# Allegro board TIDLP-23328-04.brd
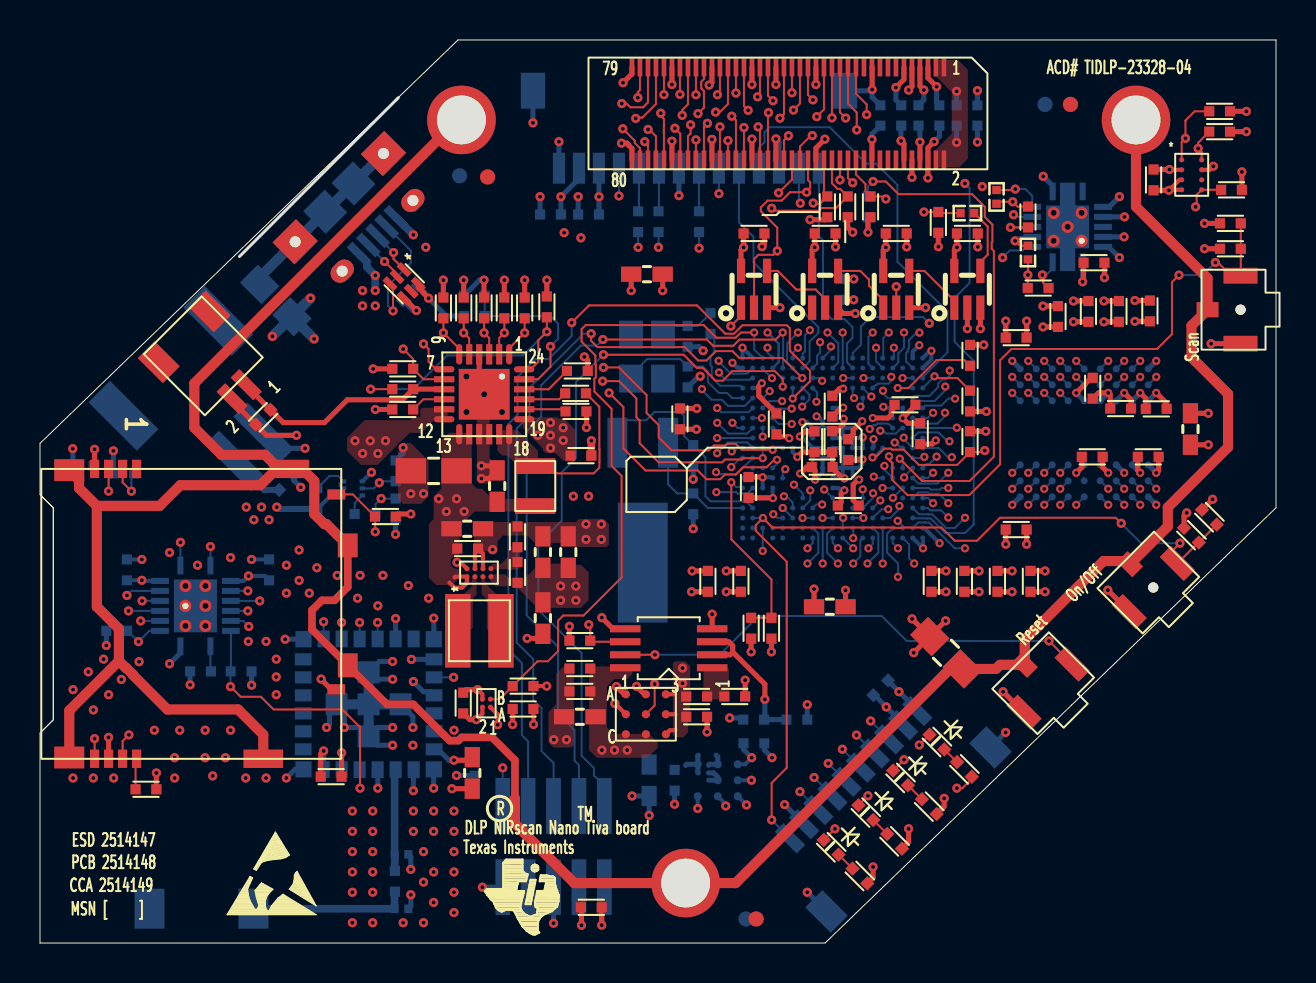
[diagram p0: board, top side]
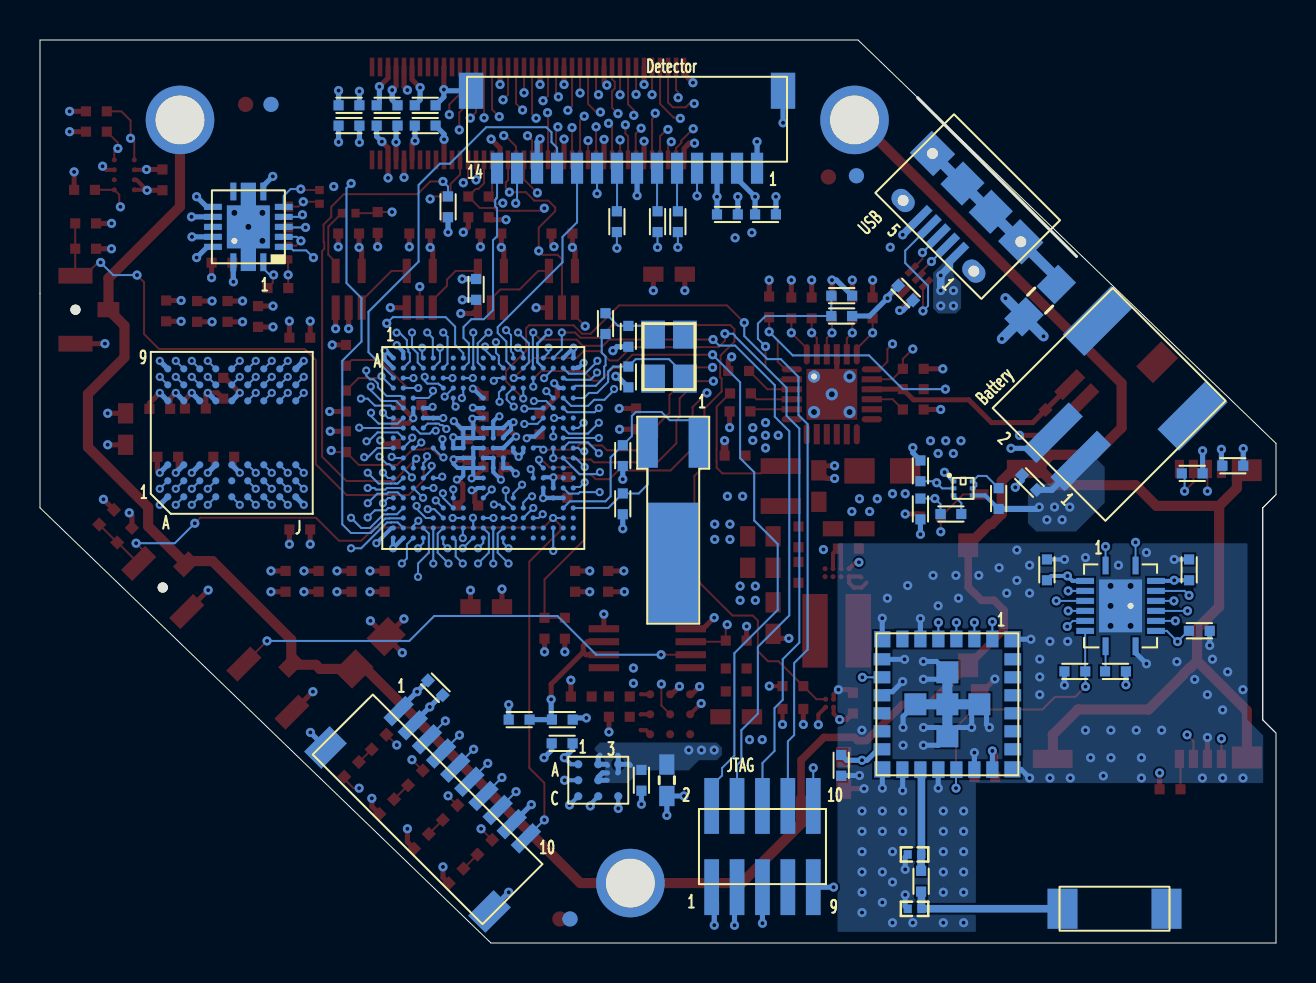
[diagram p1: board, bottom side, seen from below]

Outline 61.81 x 45.18 mm; copper layers: TOP, LY2-GND, LY3-SIG, LY4-SIG, LY5-PWR, LY6-PWR, LY7-SIG, LY8-SIG, LY9-GND, BOTTOM. Coordinates in mm from the lower left corner of the outline.
Outline path: 0,25 20.9,45.18 61.81,45.18 61.81,32.49 61.81,21.78 51.59,11.91 39.25,0 0,0 0,10.5 0.66,11.17 0.66,21.77 0,22.43 0,25

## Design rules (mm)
net group BT-ANT: nets BT_ANT BT_ANTENNA
net group USB_DAT: nets USB_DAT_N USB_DAT_P
net group CLK: nets HSYNC_CS PCLK SDR_CLK VSYNC_WE VSYNC_WE_B
net group PDATA: nets DATAEN_CMD DATAEN_CMD_B PDATA_00 PDATA_01 PDATA_02 PDATA_03 PDATA_04 PDATA_05 PDATA_06 PDATA_07 PDATA_08 PDATA_09 PDATA_10 PDATA_11 PDATA_12 PDATA_13 PDATA_14 PDATA_15 PDATA_16 PDATA_17 PDATA_18 PDATA_19 PDATA_20 PDATA_21 PDATA_22 PDATA_23
net group PWR: nets BATTERY_THERMISTOR
net group SDR: nets SDR_AD00 SDR_AD01 SDR_AD02 SDR_AD03 SDR_AD04 SDR_AD05 SDR_AD06 SDR_AD07 SDR_AD08 SDR_AD09 SDR_AD10 SDR_AD11 SDR_AD12 SDR_AD13 SDR_AD14 SDR_AD15 SDR_CASZ SDR_CKE SDR_CSZ SDR_LDQM SDR_RASZ SDR_UDQM SDR_WEZ

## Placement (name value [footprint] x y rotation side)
C1  -  [0402]  48.81 20.69 0 top
C2  -  [0402]  52.64 27.75 270 top
C3  -  [0402]  52.62 24.32 180 top
C4  -  [0402]  55.42 24.32 0 top
C5  -  [0402]  55.82 26.72 180 top
C6  -  [0402]  48.81 30.29 0 top
C7  -  [0402]  54.04 26.74 180 top
C8  -  [0603]  57.53 25.71 270 top
C10  -  [0402]  2.16 23.88 180 bottom
C11  -  [0402]  21.74 8.89 270 bottom
C12  -  [0603]  21.62 8.51 270 top
C13  -  [0402]  14.56 8.32 0 top
C14  -  [0402]  18.52 32.52 225 bottom
C15  -  [0402]  11.46 18.67 90 bottom
C17  -  [0201]  18.08 4.43 180 bottom
C18  -  [0201]  18.07 1.71 180 bottom
C19  -  [0402]  4.34 18.67 90 bottom
C20  -  [0402]  21.16 12.01 90 top
C21  -  [0402]  25.53 36.45 180 bottom
C22  -  [0402]  27.43 36.45 180 bottom
C23  -  [0402]  55.68 38.18 270 top
C24  -  [0402]  24.16 11.71 0 top
C25  -  [0402]  42.04 12.77 225 bottom
C26  -  [0402]  59.52 36 180 top
C27  -  [0402]  58.48 21.3 135 top
C28  -  [0402]  27.57 1.79 180 top
C29  -  [0402]  32.66 24.38 90 bottom
C30  -  [0402]  32.66 21.97 90 bottom
C32  -  [0402]  35.56 15.75 270 top
C33  -  [0402]  40.41 24.69 270 top
C34  -  [0402]  39.61 25.09 270 top
C35  -  [0402]  39.11 23.81 0 top
C36  -  [0402]  38.73 25.08 270 top
C37  -  [0402]  44.57 18.09 90 top
C38  -  [0402]  46.22 18.09 90 top
C39  -  [0402]  47.87 18.09 90 top
C40  -  [0402]  49.53 18.09 90 top
C41  -  [0402]  40.41 21.89 0 top
C42  -  [0402]  35.43 22.79 270 top
C43  -  [0402]  33.4 18.09 90 top
C44  -  [0402]  35.05 18.09 90 top
C45  -  [0603]  30.35 33.46 0 top
C46  -  [0402]  50.9 31.34 90 top
C47  -  [0402]  52.43 31.6 90 top
C48  -  [0402]  53.95 31.6 90 top
C49  -  [0402]  55.5 31.62 90 top
C50  -  [0603]  39.49 16.82 0 top
C51  -  [0402]  36.83 25.97 90 top
C52  -  [0402]  39.62 26.86 270 top
C53  -  [0402]  40 32.7 270 bottom
C54  -  [0402]  32 26.22 90 top
C55  -  [0402]  52.7 34.04 0 top
C56  -  [0402]  42.55 41.91 180 bottom
C57  -  [0402]  44.45 41.91 0 bottom
C58  -  [0402]  46.35 40.89 0 bottom
C59  -  [0402]  46.35 41.91 0 bottom
C60  -  [0402]  44.45 40.89 0 bottom
C61  -  [0402]  42.55 40.89 180 bottom
C62  -  [0402]  27.05 24.38 0 top
C63  -  [0402]  26.78 27.5 0 top
C64  -  [0805]  19.68 23.62 0 top
C65  -  [0603]  22.86 22.86 90 top
C66  -  [0402]  21.38 19.73 0 top
C67  -  [0603]  21.36 20.72 0 top
C68  -  [0603]  25.15 16.26 270 top
C69  -  [0603]  26.42 19.56 90 top
C70  -  [0603]  25.15 19.56 90 top
C71  -  [0402]  12.33 23.04 225 bottom
C72  -  [0402]  25.34 31.83 270 top
C73  -  [0402]  31.73 8.14 270 bottom
C74  -  [0603]  30.46 8.14 270 bottom
C75  -  [0402]  35.7 9.99 180 bottom
C76  -  [0402]  26.99 13.73 180 top
C77  -  [0402]  26.8 26.6 180 top
C78  -  [0402]  26.99 12.59 180 top
C79  -  [0603]  26.99 11.32 180 top
C80  -  [0402]  32.84 11.32 180 top
C81  -  [0402]  35.7 35.5 0 top
C82  -  [0402]  39.26 35.5 0 top
C83  -  [0402]  42.82 35.5 0 top
C84  -  [0402]  46.37 35.5 0 top
C85  -  [0402]  43.25 26.93 0 top
C86  -  [0402]  44.01 25.49 270 top
C87  -  [0402]  32.38 28.32 90 bottom
C88  -  [0402]  32.38 30.35 90 bottom
D1  -  [0402DIO]  43.03 8.26 135 top
D2  -  [0402DIO]  41.3 6.53 135 top
D3  -  [0402DIO]  39.56 4.79 135 top
D4  -  [0402DIO]  44.85 10.05 135 top
E1  -  [MOD2-BT-WIFI-LTA-5320_MAG]  8.07 1.71 180 bottom
F1  -  [0805]  11.79 32.14 315 bottom
FID  -  [unnamed#2]  22.38 38.32 0 top
FID#2  -  [unnamed#2]  35.81 1.2 0 top
FID#3  -  [unnamed#2]  51.53 41.95 0 top
FID#4  -  [unnamed#2]  50.26 41.95 180 bottom
FID#5  -  [unnamed#2]  35.3 1.2 180 bottom
FID#6  -  [unnamed#2]  20.98 38.38 180 bottom
J1  -  [CONN5-MICRO-USB-10118194_FCI]  14.97 37.29 45 bottom
J2  -  [CONN14-SM14B-SRSS-TB_JST]  32.45 38.76 180 bottom
J3  -  [CONN10-SM10B-SRSS-TB_JST]  40.69 8.42 45 bottom
J4  -  [CONN10-FTSH-105-01-L-DV-K_SAM]  25.68 4.83 180 bottom
J5  -  [CONN80-SS4_SAM]  37.4 41.5 0 top
J6  -  [CONN2-S2B-PH-SM4-TB_JST]  8.52 26.77 225 bottom
J7  -  [CONN2-SM02B-SRSS-TB_JST]  9.96 27.58 225 top
L1  -  [IND-LPS3015_COIL]  21.97 15.62 0 top
L2  -  [IND-2520_TOKO]  24.77 22.86 270 top
L3  -  [0402]  17.75 3.09 270 bottom
MH1  -  [135RD96]  21.08 41.18 0 top
MH2  -  [135RD96]  54.81 41.18 0 top
MH3  -  [135RD96]  32.28 3 0 top
NOREF  -  []  104.7 -1.3 0 top
NOREF#2  -  []  0.66 21.77 0 top
NOREF#3  -  []  0 10.5 0 top
NOREF#4  -  []  78.98 -18.04 180 top
NOREF#5  -  []  20.9 45.18 0 top
NOREF#6  -  []  0 22.43 0 top
NOREF#7  -  []  0.66 11.17 0 top
NOREF#8  -  []  24.15 2.55 0 top
NOREF#9  -  []  61.81 21.78 0 top
NOREF#10  -  []  0.66 21.77 0 top
NOREF#11  -  []  -21.27 74.61 180 top
NOREF#12  -  []  -83.31 -55.55 0 top
NOREF#13  -  []  20.9 45.18 0 top
NOREF#14  -  []  0 0 0 top
NOREF#15  -  []  39.25 0 0 top
NOREF#16  -  []  78.9 74.61 180 top
NOREF#17  -  []  61.81 21.78 0 top
NOREF#18  -  []  0 0 0 top
NOREF#19  -  []  0 25 0 top
NOREF#20  -  []  11.83 3.2 0 top
P1  -  [CONN8-SCHA-MICRO-SD-B0200_ALPS]  7.56 16.47 270 top
R1  -  [0402]  23.22 31.77 90 top
R2  -  [0402]  20.17 31.77 90 top
R3  -  [0402]  21.19 31.77 90 top
R4  -  [0402]  18.14 28.73 180 top
R5  -  [0402]  4.19 23.5 180 bottom
R6  -  [0402]  5.3 7.69 0 top
R7  -  [0402]  17.27 21.34 0 top
R8  -  [0402]  24.24 31.77 270 top
R9  -  [0402]  22.2 31.77 270 top
R11  -  [0402]  8.03 13.59 180 bottom
R12  -  [0402]  3.84 15.62 180 bottom
R13  -  [0402]  10.06 13.59 0 bottom
R14  -  [0402]  29.91 36.09 270 bottom
R15  -  [0402]  30.93 36.09 270 bottom
R16  -  [0402]  32.96 36.09 270 bottom
R17  -  [0402]  41.53 36.83 270 top
R18  -  [0402]  59.58 37.68 0 top
R19  -  [0402]  58.99 40.59 0 top
R20  -  [0402]  58.99 41.61 0 top
R21  -  [0402]  24.16 12.85 180 top
R22  -  [0402]  44.47 6.82 315 top
R23  -  [0402]  42.73 5.09 315 top
R24  -  [0402]  41 3.35 315 top
R25  -  [0402]  46.51 29.4 90 top
R26  -  [0402]  46.51 27.12 270 top
R27  -  [0402]  59.52 34.73 180 top
R28  -  [0402]  57.58 20.41 135 top
R30  -  [0402]  33.53 30.99 90 bottom
R31  -  [0402]  46.51 25.08 270 top
R32  -  [0402]  36.58 15.75 270 top
R33  -  [0201]  47.83 37.33 270 top
R34  -  [0201]  49.4 34.54 270 top
R35  -  [0402]  39.37 36.83 270 top
R36  -  [0402]  40.39 36.83 270 top
R37  -  [0402]  41.4 36.83 270 bottom
R38  -  [0402]  49.91 32.77 180 top
R39  -  [0402]  49.4 36.32 90 top
R40  -  [0402]  23.88 18.54 90 top
R41  -  [0402]  23.88 20.32 90 top
R42  -  [0402]  46.22 8.69 315 top
R43  -  [0402]  35.69 11.18 0 bottom
R44  -  [0402]  18.14 27.71 0 top
R45  -  [0402]  26.99 15.13 0 top
R46  -  [0402]  37.85 11.18 180 bottom
R47  -  [0402]  11.16 26.3 225 top
R48  -  [0402]  26.87 28.62 180 top
R49  -  [0402]  18.14 26.69 0 top
R50  -  [0402]  32.84 12.33 0 top
R51  -  [0402]  34.74 12.33 180 top
R52  -  [0201]  46.37 36.52 0 top
R53  -  [0402]  44.92 36.05 90 top
R54  -  [0402]  17.78 21.72 90 bottom
R55  -  [0402]  17.78 23.62 90 bottom
R56  -  [0402]  13.87 22.24 270 bottom
R57  -  [0402]  16.26 21.46 180 bottom
R58  -  [0805]  45.3 14.52 135 top
R59  -  [0402]  21.72 31.37 0 bottom
R60  -  [0402]  21.72 32.38 180 bottom
SW1  -  [SW3-B3U-3100P-B_OMR]  60.03 31.68 270 top
SW2  -  [SW3-B3U-3100P-B_OMR]  55.67 17.79 225 top
SW3  -  [SW3-B3U-3100P_OMR]  50.41 12.75 225 top
U1  -  [BGA212-ZAD_TI]  39.64 24.77 180 bottom
U2  -  [BGA54_MICRON]  52.22 25.52 90 bottom
U3  -  [SOIC6-DRY_TI]  18.21 32.98 225 top
U4  -  [PQFP16-RGY_TI]  7.77 16.87 270 bottom
U5  -  [MOD24-MOE_TI]  16.43 11.94 0 bottom
U6  -  [BGA8-YPA008_TI]  57.59 38.43 0 top
U7  -  [BGA4-YFP_TI]  22.32 12 180 top
U9  -  [PQFP14-RGY_TI]  51.39 35.83 90 bottom
U10  -  [PQFP24-RGE_TI]  22.21 27.45 270 top
U11  -  [BGA8-YFG_TI]  21.95 18.53 90 top
U12  -  [BGA8-SIP_TI]  33.89 8.14 180 bottom
U13  -  [SOIC8-DGK_TI]  31.44 14.75 90 top
U14  -  [BGA9-SIP_TI]  30.3 11.44 0 top
U15  -  [SOIC5_DCK_TI]  35.7 32.71 0 top
U16  -  [SOIC5_DCK_TI]  39.26 32.71 0 top
U17  -  [SOIC5_DCK_TI]  42.82 32.71 0 top
U18  -  [SOIC5_DCK_TI]  46.37 32.71 0 top
U19  -  [SOIC6-SOT963_DIO]  15.65 22.75 270 bottom
Y1  -  [CRY3-CMR200T_CIT]  30.14 21.15 90 bottom
Y2  -  [CRY-NX3225A_NDK]  30.35 29.34 90 bottom

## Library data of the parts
C1-C7 C10 C11 C13-C15 C19-C30 C32-C44 C46-C49 C51-C63 C66 C71-C73 C75-C78 C80-C88 L3 R1-R9 R11-R28 R30-R32 R35-R51 R53-R57 R59 R60 = 0402: alternate symbols: (0402-1mm)
C8 C12 C45 C50 C65 C67-C70 C74 C79 = 0603
C17 C18 R33 R34 R52 = 0201: alternate symbols: (0402-1mm)
C64 F1 R58 = 0805
D1-D4 = 0402DIO
E1 = MOD2-BT-WIFI-LTA-5320_MAG
J1 = CONN5-MICRO-USB-10118194_FCI
J2 = CONN14-SM14B-SRSS-TB_JST
J3 = CONN10-SM10B-SRSS-TB_JST
J4 = CONN10-FTSH-105-01-L-DV-K_SAM
J5 = CONN80-SS4_SAM
J6 = CONN2-S2B-PH-SM4-TB_JST
J7 = CONN2-SM02B-SRSS-TB_JST
L1 = IND-LPS3015_COIL
L2 = IND-2520_TOKO
MH1-MH3 = 135RD96
P1 = CONN8-SCHA-MICRO-SD-B0200_ALPS
SW1 SW2 = SW3-B3U-3100P-B_OMR
SW3 = SW3-B3U-3100P_OMR
U1 = BGA212-ZAD_TI
U2 = BGA54_MICRON
U3 = SOIC6-DRY_TI
U4 = PQFP16-RGY_TI
U5 = MOD24-MOE_TI
U6 = BGA8-YPA008_TI
U7 = BGA4-YFP_TI
U9 = PQFP14-RGY_TI
U10 = PQFP24-RGE_TI
U11 = BGA8-YFG_TI
U12 = BGA8-SIP_TI
U13 = SOIC8-DGK_TI
U14 = BGA9-SIP_TI
U15-U18 = SOIC5_DCK_TI
U19 = SOIC6-SOT963_DIO
Y1 = CRY3-CMR200T_CIT
Y2 = CRY-NX3225A_NDK

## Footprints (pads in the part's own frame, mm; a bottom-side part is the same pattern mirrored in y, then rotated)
135RD96
  round 3.429 hole 2.438: 1(0,0)
0201
  rect 0.406x0.432 smd: 1(-0.343,0) 2(0.343,0)
0402
  rect 0.508x0.508 smd: 1(-0.521,0) 2(0.521,0)
0402DIO
  rect 0.508x0.508 smd: 1(-0.521,0) 2(0.521,0)
0603
  rect 1.016x0.762 smd: 1(-0.787,0) 2(0.787,0)
0805
  rect 1.524x1.27 smd: 1(-1.143,0) 2(1.143,0)
BGA4-YFP_TI
  round 0.254 smd: A1(-0.2,0.2) A2(0.2,0.2) B1(-0.2,-0.2) B2(0.2,-0.2)
BGA8-SIP_TI
  round 0.406 smd: A1(-1,0.8) A2(0,0.8) A3(1,0.8) B1(-1,0) B2(0,0) C1(-1,-0.8) C2(0,-0.8) C3(1,-0.8)
BGA8-YFG_TI
  round 0.254 smd: A1(-0.2,0.6) A2(0.2,0.6) B1(-0.2,0.2) B2(0.2,0.2) C1(-0.2,-0.2) C2(0.2,-0.2) D1(-0.2,-0.6) D2(0.2,-0.6)
BGA8-YPA008_TI
  round 0.254 smd: A1(-0.5,0.75) A2(0.5,0.75) B1(-0.5,0.25) B2(0.5,0.25) C1(-0.5,-0.25) C2(0.5,-0.25) D1(-0.5,-0.75) D2(0.5,-0.75)
BGA9-SIP_TI
  round 0.406 smd: A1(-1,1) A2(0,1) A3(1,1) B1(-1,0) B2(0,0) B3(1,0) C1(-1,-1) C2(0,-1) C3(1,-1)
BGA54_MICRON
  round 0.356 smd: A1(-3.2,3.2) A2(-2.4,3.2) A3(-1.6,3.2) A7(1.6,3.2) A8(2.4,3.2) A9(3.2,3.2) B1(-3.2,2.4) B2(-2.4,2.4) B3(-1.6,2.4) B7(1.6,2.4) B8(2.4,2.4) B9(3.2,2.4) C1(-3.2,1.6) C2(-2.4,1.6) C3(-1.6,1.6) C7(1.6,1.6) C8(2.4,1.6) C9(3.2,1.6) D1(-3.2,0.8) D2(-2.4,0.8) D3(-1.6,0.8) D7(1.6,0.8) D8(2.4,0.8) D9(3.2,0.8) E1(-3.2,0) E2(-2.4,0) E3(-1.6,0) E7(1.6,0) E8(2.4,0) E9(3.2,0) F1(-3.2,-0.8) F2(-2.4,-0.8) F3(-1.6,-0.8) F7(1.6,-0.8) F8(2.4,-0.8) F9(3.2,-0.8) G1(-3.2,-1.6) G2(-2.4,-1.6) G3(-1.6,-1.6) G7(1.6,-1.6) G8(2.4,-1.6) G9(3.2,-1.6) H1(-3.2,-2.4) H2(-2.4,-2.4) H3(-1.6,-2.4) H7(1.6,-2.4) H8(2.4,-2.4) H9(3.2,-2.4) J1(-3.2,-3.2) J2(-2.4,-3.2) J3(-1.6,-3.2) J7(1.6,-3.2) J8(2.4,-3.2) J9(3.2,-3.2)
BGA212-ZAD_TI
  round 0.254 smd: A1(-4.5,4.5) A2(-4,4.5) A4(-3,4.5) A5(-2.5,4.5) A7(-1.5,4.5) A8(-1,4.5) A10(0,4.5) A11(0.5,4.5) A13(1.5,4.5) A14(2,4.5) A16(3,4.5) A17(3.5,4.5) A18(4,4.5) A19(4.5,4.5) B1(-4.5,4) B2(-4,4) B3(-3.5,4) B4(-3,4) B5(-2.5,4) B6(-2,4) B7(-1.5,4) B8(-1,4) B9(-0.5,4) B10(0,4) B11(0.5,4) B12(1,4) B13(1.5,4) B14(2,4) B15(2.5,4) B16(3,4) B17(3.5,4) B18(4,4) B19(4.5,4) C1(-4.5,3.5) C2(-4,3.5) C5(-2.5,3.5) C6(-2,3.5) C8(-1,3.5) C10(0,3.5) C12(1,3.5) C14(2,3.5) C15(2.5,3.5) C18(4,3.5) D1(-4.5,3) D2(-4,3) D6(-2,3) D7(-1.5,3) D8(-1,3) D12(1,3) D13(1.5,3) D14(2,3) D18(4,3) D19(4.5,3) E2(-4,2.5) E3(-3.5,2.5) E7(-1.5,2.5) E10(0,2.5) E13(1.5,2.5) E17(3.5,2.5) E18(4,2.5) E19(4.5,2.5) F1(-4.5,2) F2(-4,2) F3(-3.5,2) F4(-3,2) F10(0,2) F16(3,2) F17(3.5,2) F18(4,2) G1(-4.5,1.5) G2(-4,1.5) G4(-3,1.5) G5(-2.5,1.5) G10(0,1.5) G15(2.5,1.5) G16(3,1.5) G18(4,1.5) G19(4.5,1.5) H2(-4,1) H3(-3.5,1) H4(-3,1) H9(-0.5,1) H10(0,1) H11(0.5,1) H12(1,1) H16(3,1) H17(3.5,1) H18(4,1) H19(4.5,1) J1(-4.5,0.5) J2(-4,0.5) J8(-1,0.5) J9(-0.5,0.5) J10(0,0.5) J11(0.5,0.5) J12(1,0.5) J18(4,0.5) K1(-4.5,0) K2(-4,0) K3(-3.5,0) K5(-2.5,0) K6(-2,0) K7(-1.5,0) K8(-1,0) K9(-0.5,0) K10(0,0) K11(0.5,0) K12(1,0) K13(1.5,0) K14(2,0) K15(2.5,0) K17(3.5,0) K18(4,0) K19(4.5,0) L2(-4,-0.5) L8(-1,-0.5) L9(-0.5,-0.5) L10(0,-0.5) L11(0.5,-0.5) L12(1,-0.5) L18(4,-0.5) L19(4.5,-0.5) M1(-4.5,-1) M2(-4,-1) M3(-3.5,-1) M4(-3,-1) M8(-1,-1) M9(-0.5,-1) M10(0,-1) M11(0.5,-1) M12(1,-1) M16(3,-1) M17(3.5,-1) M18(4,-1) N1(-4.5,-1.5) N2(-4,-1.5) N4(-3,-1.5) N5(-2.5,-1.5) N10(0,-1.5) N15(2.5,-1.5) N16(3,-1.5) N18(4,-1.5) N19(4.5,-1.5) P2(-4,-2) P3(-3.5,-2) P4(-3,-2) P10(0,-2) P16(3,-2) P17(3.5,-2) P18(4,-2) P19(4.5,-2) R1(-4.5,-2.5) R2(-4,-2.5) R3(-3.5,-2.5) R7(-1.5,-2.5) R10(0,-2.5) R13(1.5,-2.5) R17(3.5,-2.5) R18(4,-2.5) T1(-4.5,-3) T2(-4,-3) T6(-2,-3) T7(-1.5,-3) T8(-1,-3) T12(1,-3) T13(1.5,-3) T14(2,-3) T18(4,-3) T19(4.5,-3) U2(-4,-3.5) U5(-2.5,-3.5) U6(-2,-3.5) U8(-1,-3.5) U10(0,-3.5) U12(1,-3.5) U14(2,-3.5) U15(2.5,-3.5) U18(4,-3.5) U19(4.5,-3.5) V1(-4.5,-4) V2(-4,-4) V3(-3.5,-4) V4(-3,-4) V5(-2.5,-4) V6(-2,-4) V7(-1.5,-4) V8(-1,-4) V9(-0.5,-4) V10(0,-4) V11(0.5,-4) V12(1,-4) V13(1.5,-4) V14(2,-4) V15(2.5,-4) V16(3,-4) V17(3.5,-4) V18(4,-4) V19(4.5,-4) W1(-4.5,-4.5) W2(-4,-4.5) W3(-3.5,-4.5) W4(-3,-4.5) W6(-2,-4.5) W7(-1.5,-4.5) W9(-0.5,-4.5) W10(0,-4.5) W12(1,-4.5) W13(1.5,-4.5) W15(2.5,-4.5) W16(3,-4.5) W18(4,-4.5) W19(4.5,-4.5)
CONN2-S2B-PH-SM4-TB_JST
  rect 1.524x3.429 smd: (-3.35,2.8) (3.35,2.8)
  rect 1x3.29 smd: 1(1,-2.75) 2(-1,-2.75)
CONN2-SM02B-SRSS-TB_JST
  rect 1.194x1.778 smd: (-1.8,-3.886) (1.8,-3.886)
  rect 0.61x1.6 smd: 1(-0.5,0) 2(0.5,0)
CONN5-MICRO-USB-10118194_FCI
  rect 0.406x1.372 smd: 1(-1.3,2.7) 2(-0.65,2.7) 3(0,2.7) 4(0.65,2.7) 5(1.3,2.7)
  rect 1.65x1.55 hole 0.55: 6(3.122,0) 9(-3.122,0)
  rect 1.524x1.6 smd: 7(1,0) 8(-1,0)
  oval 1.25x0.95 hole 0.55: 10(2.5,2.7) 11(-2.5,2.7)
CONN8-SCHA-MICRO-SD-B0200_ALPS
  rect 0.914x0.457 smd: 1(-7.25,-2.735) 2(-7.25,-3.435) 3(-7.25,-4.135) 4(-7.25,-4.835) 5(7.25,-4.835) 6(7.25,-4.135) 7(7.25,-3.435) 8(7.25,-2.735)
  rect 0.914x1.981 smd: 9(7.25,3.6) 14(-7.25,4.9)
  rect 0.508x0.889 smd: 10(3.775,7.25) 13(-5.975,7.25)
  rect 1.194x0.991 smd: 11(2.575,7.825) 12(-3.425,7.825)
  rect 1.092x1.499 smd: 15(-7.187,-6.1) 16(7.187,-6.1)
CONN10-FTSH-105-01-L-DV-K_SAM
  rect 0.737x2.794 smd: 1(-2.54,-2.032) 2(-2.54,2.032) 3(-1.27,-2.032) 4(-1.27,2.032) 5(0,-2.032) 6(0,2.032) 7(1.27,-2.032) 8(1.27,2.032) 9(2.54,-2.032) 10(2.54,2.032)
CONN10-SM10B-SRSS-TB_JST
  rect 0.61x1.549 smd: 1(4.5,0) 2(3.5,0) 3(2.5,0) 4(1.5,0) 5(0.5,0) 6(-0.5,0) 7(-1.5,0) 8(-2.5,0) 9(-3.5,0) 10(-4.5,0)
  rect 1.219x1.803 smd: 11(-5.8,3.875) 12(5.8,3.875)
CONN14-SM14B-SRSS-TB_JST
  rect 0.61x1.549 smd: 1(6.5,0) 2(5.5,0) 3(4.5,0) 4(3.5,0) 5(2.5,0) 6(1.5,0) 7(0.5,0) 8(-0.5,0) 9(-1.5,0) 10(-2.5,0) 11(-3.5,0) 12(-4.5,0) 13(-5.5,0) 14(-6.5,0)
  rect 1.219x1.803 smd: 15(-7.8,3.875) 16(7.8,3.875)
CONN80-SS4_SAM
  rect 0.229x0.94 smd: 1(7.801,2.324) 2(7.801,-2.324) 3(7.401,2.324) 4(7.401,-2.324) 5(7.001,2.324) 6(7.001,-2.324) 7(6.601,2.324) 8(6.601,-2.324) 9(6.201,2.324) 10(6.201,-2.324) 11(5.801,2.324) 12(5.801,-2.324) 13(5.401,2.324) 14(5.401,-2.324) 15(5.001,2.324) 16(5.001,-2.324) 17(4.601,2.324) 18(4.601,-2.324) 19(4.201,2.324) 20(4.201,-2.324) 21(3.801,2.324) 22(3.801,-2.324) 23(3.401,2.324) 24(3.401,-2.324) 25(3.001,2.324) 26(3.001,-2.324) 27(2.6,2.324) 28(2.6,-2.324) 29(2.2,2.324) 30(2.2,-2.324) 31(1.8,2.324) 32(1.8,-2.324) 33(1.4,2.324) 34(1.4,-2.324) 35(1,2.324) 36(1,-2.324) 37(0.6,2.324) 38(0.6,-2.324) 39(0.2,2.324) 40(0.2,-2.324) 41(-0.2,2.324) 42(-0.2,-2.324) 43(-0.6,2.324) 44(-0.6,-2.324) 45(-1,2.324) 46(-1,-2.324) 47(-1.4,2.324) 48(-1.4,-2.324) 49(-1.8,2.324) 50(-1.8,-2.324) 51(-2.2,2.324) 52(-2.2,-2.324) 53(-2.6,2.324) 54(-2.6,-2.324) 55(-3,2.324) 56(-3,-2.324) 57(-3.4,2.324) 58(-3.4,-2.324) 59(-3.8,2.324) 60(-3.8,-2.324) 61(-4.2,2.324) 62(-4.2,-2.324) 63(-4.6,2.324) 64(-4.6,-2.324) 65(-5,2.324) 66(-5,-2.324) 67(-5.401,2.324) 68(-5.401,-2.324) 69(-5.801,2.324) 70(-5.801,-2.324) 71(-6.201,2.324) 72(-6.201,-2.324) 73(-6.601,2.324) 74(-6.601,-2.324) 75(-7.001,2.324) 76(-7.001,-2.324) 77(-7.401,2.324) 78(-7.401,-2.324) 79(-7.801,2.324) 80(-7.801,-2.324)
CRY3-CMR200T_CIT
  rect 6x2.5 smd: (-2.125,0)
  rect 2.5x1 smd: 1(3.875,-1.27) 2(3.875,1.27)
CRY-NX3225A_NDK
  rect 1.397x1.194 smd: 1(-1.1,-0.8) 2(1.1,-0.8) 3(1.1,0.8) 4(-1.1,0.8)
IND-2520_TOKO
  rect 0.787x2.007 smd: 1(-1,0) 2(1,0)
IND-LPS3015_COIL
  rect 1.27x3.683 smd: 1(-1.079,0) 2(1.079,0)
MOD2-BT-WIFI-LTA-5320_MAG
  rect 1.499x2.007 smd: 1(-2.6,0) 2(2.6,0)
MOD24-MOE_TI
  rect 0.61x0.838 smd: 1(-2.25,-3.269) 2(-1.35,-3.269) 3(-0.45,-3.269) 4(0.45,-3.269) 5(1.35,-3.269) 6(2.25,-3.269) 13(2.25,3.269) 14(1.35,3.269) 15(0.45,3.269) 16(-0.45,3.269) 17(-1.35,3.269) 18(-2.25,3.269)
  rect 0.838x0.61 smd: 7(3.269,-2.25) 8(3.269,-1.35) 9(3.269,-0.45) 10(3.269,0.45) 11(3.269,1.35) 12(3.269,2.25) 19(-3.269,2.25) 20(-3.269,1.35) 21(-3.269,0.45) 22(-3.269,-0.45) 23(-3.269,-1.35) 24(-3.269,-2.25)
  rect 1.1x1.1 smd: 25(0,-1.6) 26(-1.6,0) 27(0,0) 28(1.6,0) 29(0,1.6)
  rect 0.813x0.813 smd: 30(-3.256,-3.256) 31(3.256,-3.256) 32(3.256,3.256) 33(-3.256,3.256)
PQFP14-RGY_TI
  rect 0.889x0.305 smd: 1(-1.77,-0.75) 7(1.77,-0.75) 8(1.77,0.75) 14(-1.77,0.75)
  rect 0.305x0.889 smd: 2(-1,-1.77) 3(-0.5,-1.77) 4(0,-1.77) 5(0.5,-1.77) 6(1,-1.77) 9(1,1.77) 10(0.5,1.77) 11(0,1.77) 12(-0.5,1.77) 13(-1,1.77)
  round 0.61 hole 0.305: 15(-0.7,0.7)
PQFP16-RGY_TI
  rect 0.889x0.305 smd: 1(-2.02,-0.75) 8(2.02,-0.75) 9(2.02,0.75) 16(-2.02,0.75)
  rect 0.305x0.889 smd: 2(-1.25,-1.77) 3(-0.75,-1.77) 4(-0.25,-1.77) 5(0.25,-1.77) 6(0.75,-1.77) 7(1.25,-1.77) 10(1.25,1.77) 11(0.75,1.77) 12(0.25,1.77) 13(-0.25,1.77) 14(-0.75,1.77) 15(-1.25,1.77)
  round 0.61 hole 0.305: 17(0,0.5)
PQFP24-RGE_TI
  oval 1.016x0.305 smd: 1(-2,1.25) 6(-2,-1.25) 13(2,-1.25) 18(2,1.25)
  rect 1.016x0.305 smd: 2(-2,0.75) 3(-2,0.25) 4(-2,-0.25) 5(-2,-0.75) 14(2,-0.75) 15(2,-0.25) 16(2,0.25) 17(2,0.75)
  oval 0.305x1.016 smd: 7(-1.25,-2) 12(1.25,-2) 19(1.25,2) 24(-1.25,2)
  rect 0.305x1.016 smd: 8(-0.75,-2) 9(-0.25,-2) 10(0.25,-2) 11(0.75,-2) 20(0.75,2) 21(0.25,2) 22(-0.25,2) 23(-0.75,2)
  round 0.61 hole 0.305: 25(-0.889,0.889)
SOIC5_DCK_TI
  rect 0.406x1.219 smd: 1(-0.65,-0.92) 2(0,-0.92) 3(0.65,-0.92) 4(0.65,0.92) 5(-0.65,0.92)
SOIC6-DRY_TI
  rect 0.305x0.762 smd: 1(-0.5,-0.506) 2(0,-0.506) 3(0.5,-0.506) 4(0.513,0.506) 5(0.013,0.506) 6(-0.487,0.506)
SOIC6-SOT963_DIO
  rect 0.203x0.279 smd: 1(-0.35,-0.475) 2(0,-0.475) 3(0.35,-0.475) 4(0.35,0.475) 5(0,0.475) 6(-0.35,0.475)
SOIC8-DGK_TI
  rect 0.356x1.524 smd: 1(-0.975,-2.173) 2(-0.325,-2.173) 3(0.325,-2.173) 4(0.975,-2.173) 5(0.975,2.173) 6(0.325,2.173) 7(-0.325,2.173) 8(-0.975,2.173)
SW3-B3U-3100P-B_OMR
  round 0.508 hole 0.889 unplated: (0,0)
  rect 0.787x1.702 smd: 1(-1.7,0) 2(1.7,0)
  rect 0.762x1.092 smd: 3(0,-1.65)
SW3-B3U-3100P_OMR
  rect 0.787x1.702 smd: 1(-1.7,0) 2(1.7,0)
  rect 0.762x1.092 smd: 3(0,-1.65)
unnamed#2
  round 0.762 smd: 1(0,0)

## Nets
GND: C1.2 C2.2 C3.2 C4.2 C5.2 C6.2 C7.2 C8.2 C10.2 C11.2 C12.2 C13.2 C14.2 C15.2 C17.1 C18.1 C19.2 C20.2 C21.2 C22.2 C23.2 C24.2 C25.2 C26.2 C27.2 C28.2 C29.1 C30.1 C32.2 C33.2 C34.2 C35.2 C36.2 C37.2 C38.2 C39.2 C40.2 C41.2 C42.2 C43.2 C44.2 C45.2 C46.2 C47.2 C48.2 C49.2 C50.2 C51.2 C52.2 C53.2 C54.1 C55.2 C56.2 C57.2 C58.2 C59.2 C60.2 C61.2 C62.2 C64.1 C65.2 C66.2 C67.2 C68.2 C69.2 C70.2 C71.1 C72.1 C73.2 C74.2 C75.1 C76.2 C77.1 C78.2 C79.2 C80.1 C81.2 C82.2 C83.2 C84.2 C85.1 C86.2 C87.1 C88.1 F1.2 J1.5 J2.1 J2.7 J2.12 J2.15 J2.16 J3.2 J3.9 J3.11 J3.12 J4.3 J4.5 J4.9 J5.5 J5.6 J5.9 J5.10 J5.19 J5.20 J5.33 J5.34 J5.43 J5.44 J5.49 J5.50 J5.59 J5.60 J5.69 J5.70 J5.79 J5.80 J6.2 J7.2 P1.6 P1.10 R8.1 R9.1 R12.2 R13.2 R21.1 R31.1 R41.2 R46.1 R47.2 R48.1 R49.1 R51.1 R54.1 R55.2 R58.2 R60.2 SW1.2 SW2.2 SW3.2 U1.A1 U1.A2 U1.A18 U1.A19 U1.B1 U1.B19 U1.D18 U1.F10 U1.G4 U1.G5 U1.H10 U1.H11 U1.H12 U1.J11 U1.J12 U1.K6 U1.K9 U1.K10 U1.K13 U1.K14 U1.L8 U1.L9 U1.M8 U1.M9 U1.M10 U1.N10 U1.P16 U1.R17 U1.R18 U1.V1 U1.W1 U1.W2 U2.A1 U2.A3 U2.B7 U2.C3 U2.D7 U2.E3 U2.J1 U3.4 U4.9 U4.17 U5.5 U5.7 U5.9 U5.13 U5.15 U5.17 U5.25 U5.26 U5.27 U5.28 U5.29 U5.30 U5.31 U5.32 U5.33 U6.B2 U6.C1 U6.D1 U7.B2 U9.7 U9.9 U9.10 U9.12 U9.13 U9.15 U10.4 U10.15 U10.16 U10.25 U11.B2 U11.C2 U12.B1 U12.C1 U12.C2 U12.C3 U13.5 U14.A1 U14.A2 U14.B1 U15.3 U16.3 U17.3 U18.3 U19.1
GND_EARTH: MH1.1 MH2.1 MH3.1 P1.9 P1.11 P1.12 P1.14 P1.15 P1.16 R58.1 SW1.3 SW2.3 SW3.3
ANT_PAD: E1.2
BAT_V_SW: R54.2 R57.1 U1.A4
BAT_VSENSE_EN: R55.1 U1.B4 U19.2
BATTERY_THERMISTOR: J7.1 R44.2 R47.1 U10.9
BC_CSZ: R8.2 U1.H4 U10.1
BC_EN1: R1.1 U1.E2 U10.2
BC_EN2: R9.2 U1.E3 U10.3
BC_INT: R4.1 U1.W12 U10.8
BC_SCL: R2.1 U1.V3 U10.6
BC_SDA: R3.1 U1.W3 U10.5
BT1P8_CTS: U4.6 U5.4
BT1P8_NSHUTD: R13.1 U4.7 U5.16
BT1P8_RTS: U4.3 U5.1
BT1P8_RX: U4.5 U5.2
BT1P8_SLOW_CK: U4.1 U5.8
BT1P8_TX: U4.4 U5.3
BT_ANT: C18.2 E1.1 L3.2
BT_ANTENNA: C17.2 L3.1 U5.14
BT_CTS: U1.B12 U4.11
BT_NSHUTD: R12.1 U1.T2 U4.10
BT_RTS: U1.D8 U4.14
BT_RX: U1.C8 U4.12
BT_SLOW_CK: U1.C12 U4.16
BT_TX: U1.E7 U4.13
CSZ: J2.5 R14.1
CSZP: R14.2 U1.C6
DATAEN_CMD: R38.1 U1.N1 U9.1
DATAEN_CMD_B: J5.47 R34.2 R38.2
DIN: J2.8 R16.1
DINP: R16.2 U1.A5
DLPC_HOST_IRQ: J5.23 R37.1 U1.M3
DLPC_XLAT0_TIVA: J5.39 U1.D6
DLPC_XLAT1_TIVA: J5.41 U1.D7
DOUT_S: J2.9 U1.B5
DRDYZ: J2.10 U1.B13
EN: R52.1 R53.2 U11.A2 U14.B2
FLASH_DI_TIVA: J5.25 U1.K17
HSYNC_CS: J5.48 U1.N2
HUM_DRDYZ: R18.1 U1.A8 U6.D2
HUM_SCL: R20.1 U1.F2 U6.A1
HUM_SDA: R19.1 U1.F1 U6.A2
LI-ION_BATTERY: C71.2 J6.1 R56.2 U10.11 U10.12 U19.4
MSD_CARD_DET: P1.13 R7.1 U1.A13
MSD_CLK: P1.5 U1.T7
MSD_CSZ: P1.2 R5.1 U1.W6
MSD_DI: P1.3 U1.V6
MSD_DO: P1.7 U1.U6
OSC0: C87.2 U1.E19 Y2.1
P1P8V: C24.1 C56.1 C61.1 C75.2 J5.11 J5.12 R43.1 U7.A1 U12.A1
P1P8V_BT: C13.1 C15.1 C20.1 R11.2 U4.2 U5.18 U7.A2
P3P3V: C1.1 C2.1 C3.1 C4.1 C5.1 C6.1 C7.1 C8.1 C10.1 C11.1 C12.1 C19.1 C22.1 C23.1 C25.1 C28.1 C33.1 C34.1 C35.1 C36.1 C37.1 C38.1 C39.1 C40.1 C41.1 C42.1 C43.1 C44.1 C45.1 C46.1 C47.1 C48.1 C49.1 C50.1 C55.1 C57.1 C60.1 C68.1 C69.1 C70.1 C85.2 C86.1 J2.3 J3.1 J4.1 J5.7 J5.8 P1.4 R1.2 R2.2 R3.2 R4.2 R5.2 R6.2 R7.2 R17.2 R18.2 R19.2 R20.2 R22.2 R23.2 R24.2 R25.2 R26.2 R27.2 R28.2 R32.2 R35.2 R36.2 R37.2 R40.1 R45.1 U1.F3 U1.F4 U1.G10 U1.H9 U1.J8 U1.J9 U1.J10 U1.K7 U1.K8 U1.K11 U1.K12 U1.L10 U1.L11 U1.L12 U1.M11 U1.M12 U1.N16 U1.P10 U1.P17 U2.A7 U2.A9 U2.B3 U2.C7 U2.D3 U2.E7 U2.J9 U4.15 U5.12 U6.B1 U9.14 U11.D1 U13.4
P5P0V: C21.1 C80.2 J2.2 R50.1 U14.A3 U14.B3 U14.C3
P_LDO_V: C72.2 R42.2 R44.1 U10.24
PAD_INTZ: J5.29 U17.2
PAD_RSTZ: J5.31 U15.1
PAD_RSTZ_P3P3V: J5.28 U1.U15
PCLK: J5.45 U1.N5
PDATA_00: J5.51 U1.D13
PDATA_01: J5.52 U1.E18
PDATA_02: J5.53 U1.F18
PDATA_03: J5.54 U1.P3
PDATA_04: J5.55 U1.P2
PDATA_05: J5.56 U1.U8
PDATA_06: J5.57 U1.V8
PDATA_07: J5.58 U1.W9
PDATA_08: J5.61 U1.B14
PDATA_09: J5.62 U1.F17
PDATA_10: J5.63 U1.R10
PDATA_11: J5.64 U1.V9
PDATA_12: J5.65 U1.T13
PDATA_13: J5.66 U1.U10
PDATA_14: J5.67 U1.R13
PDATA_15: J5.68 U1.W10
PDATA_16: J5.71 U1.A14
PDATA_17: J5.72 U1.D12
PDATA_18: J5.73 U1.E17
PDATA_19: J5.74 U1.V10
PDATA_20: J5.75 U1.U12
PDATA_21: J5.76 U1.T12
PDATA_22: J5.77 U1.H17
PDATA_23: J5.78 U1.F16
PROJ_ON: J5.36 R31.2 U1.K5 U15.2
PS_EN: R52.2 U18.4
SCLK: J2.6 R15.1
SCLKP: R15.2 U1.B6
SDR_AD00: U1.P4 U2.A8 U2.H7
SDR_AD01: U1.R2 U2.B9 U2.H8
SDR_AD02: U1.R1 U2.B8 U2.J8
SDR_AD03: U1.T1 U2.C9 U2.J7
SDR_AD04: U1.K3 U2.C8 U2.J3
SDR_AD05: U1.L2 U2.D9 U2.J2
SDR_AD06: U1.M1 U2.D8 U2.H3
SDR_AD07: U1.M2 U2.E9 U2.H2
SDR_AD08: U1.V5 U2.E1 U2.H1
SDR_AD09: U1.R7 U2.D2 U2.G3
SDR_AD10: U1.T14 U2.D1 U2.H9
SDR_AD11: U1.N15 U2.C2 U2.G2
SDR_AD12: U1.L19 U2.C1 U2.G1
SDR_AD13: U1.L18 U2.B2 U2.G7
SDR_AD14: U1.K19 U2.B1 U2.G8
SDR_AD15: U1.K18 U2.A2
SDR_CASZ: U1.G18 U2.F7
SDR_CKE: U1.B10 U2.F3
SDR_CLK: U1.V17 U2.F2
SDR_CSZ: U1.A11 U2.G9
SDR_LDQM: U1.G16 U2.E8
SDR_RASZ: U1.J18 U2.F8
SDR_UDQM: U1.H19 U2.F1
SDR_WEZ: U1.B17 U2.F9
SSI0CLK_U4RX: J3.3 U1.T6
SSI0FSS_U4TX: J3.4 U1.U5
SSI0XDAT0: J3.5 U1.V4
SSI0XDAT1: J3.6 U1.W4
SW_ON/OFF: C27.1 J3.10 R28.1 SW2.1 U1.U18
SW_SCAN: C26.1 R27.1 SW1.1 U1.M4
SYNCZ: J2.4 U1.U2
SYS_PWR: C58.1 C59.1 C64.2 C65.1 C66.1 C67.1 C73.1 C74.1 C76.1 C78.1 C79.1 C81.1 C82.1 C83.1 C84.1 J5.1 J5.2 J5.3 J5.4 L2.2 R53.1 U10.13 U10.14 U11.A1 U12.A2 U12.A3 U12.B2 U13.8 U14.C1 U14.C2 U15.5 U16.5 U17.5 U18.2 U18.5
TDRDYZ: J2.14 U1.B8
TIVA_DATAEN_MASK: U1.H3 U9.2
TIVA_EXP_I2C_SCL: J5.37 R25.1 U1.D2
TIVA_EXP_I2C_SDA: J5.35 R26.1 U1.D1
TIVA_FLASH_CLK: J5.26 U1.U14
TIVA_FLASH_CSZ: J5.24 R17.1 U1.V12
TIVA_FLASH_DO: J5.27 U1.K15
TIVA_IIC0_SCL: J5.32 R35.1 U1.V11
TIVA_IIC0_SDA: J5.30 R36.1 U1.M16
TIVA_RESETZ: J4.10 R45.2 U1.P18 U13.6
TIVA_TCK: J4.4 U1.B15
TIVA_TDI: J4.8 U1.D14
TIVA_TDO: J4.6 U1.C14
TIVA_TMS: J4.2 U1.C15
TIVA_TRIG_IN_0: J5.38 U1.G1
TIVA_TRIG_IN_1: J5.40 U1.G2
TIVA_TRIG_SEL: J5.42 U1.B2
TIVA_VSYNC_MASK: U1.H2 U9.5
TSCL: J2.13 U1.C2
TSDA: J2.11 U1.C1
U4CTS: J3.8 U1.K2
U4RTS: J3.7 U1.K1
USB_DAT_N: J1.2 U1.B18 U3.2
USB_DAT_P: J1.3 U1.C18 U3.1
USB_ID: J1.4 U1.A16 U3.3
USB_VBUS: C14.1 C62.1 J1.1 R59.1 U1.B16 U3.6 U10.19
VSYNC_WE: R39.1 U1.N4 U9.4
VSYNC_WE_B: J5.46 R33.2 R39.2
XOSC0: C29.2 U1.T18 Y1.1
XOSC1: C30.2 U1.T19 Y1.2
N42370442: R48.2 U10.22
N42370449: R49.2 U10.10
N42370456: C77.2 U10.20
N42417768: C63.2 L2.1 U10.17 U10.18
N42417797: C63.1 U10.21
N42420916: R59.2 R60.1 U10.23
N42420946: D4.2 U10.7
N42420948: D4.1 R42.1
N42627229: L1.1 U11.B1
N42627251: L1.2 U11.C1
N42627428: R43.2 R46.2 U13.2 U13.3
N42627452: R50.2 R51.2 U13.1
N42627469: SW3.1 U13.7
N42627511: R40.2 R41.1 U11.D2
N43128043: U17.4 U18.1
N43128052: U16.4 U17.1
N43142748: U15.4 U16.2
N43167198: R34.1 U9.3
N43167201: R33.1 U9.6
N43219788: C51.1 C52.1 C53.1 C54.2 U1.E10 U1.H16
N43219848: C32.1 R32.1 U1.P19
N43219986: D3.1 R24.1
N43219998: D2.1 R23.1
N43220038: D1.1 R22.1
N43220044: D3.2 U1.W7
N43220071: D2.2 U1.V2
N43220075: D1.2 U1.H18
N43273215: F1.1 J1.6 J1.7 J1.8 J1.9
N43274901: R21.2 U1.A17 U7.B1
N43275105: R11.1 U4.8
N43275134: P1.8 R6.1
N43328704: R56.1 U19.5 U19.6
N43328728: R57.2 U19.3
N43392226: R30.1 U1.D19
N43392629: C88.2 R30.2 Y2.3

Pads without a net: FID 1; FID#2 1; FID#3 1; FID#4 1; FID#5 1; FID#6 1; J1 10 11; J4 7; J5 13 14 15 16 17 18 21 22; P1 1; U1 A7 A10 B3 B7 B9 B11 C5 C10 E13 G15 G19 J1 J2 M17 M18 N18 N19 R3 T8 U19 V7 V13 V14 V15 V16 V18 V19 W13 W15 W16 W18 W19; U2 E2; U3 5; U5 6 10 11 19 20 21 22 23 24; U6 C2; U9 8 11; U16 1; Y2 2 4

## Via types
v1: diameter 0.457, hole 0.203, TOP to BOTTOM, 478 vias
v2: diameter 0.406, hole 0.203, TOP to BOTTOM, 203 vias
v3: diameter 0.61, hole 0.305, TOP to BOTTOM, 13 vias

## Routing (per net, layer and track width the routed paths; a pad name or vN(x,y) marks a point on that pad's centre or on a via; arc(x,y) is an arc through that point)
GND: length 226.2
  TOP w0.203: U6.C1 56.98,38.18 56.48,37.68 U6.D1 ; U7.B2 22.12,12.45 21.9,12.67 v1(21.88,12.67) ; C24.2 v1(24.68,10.93) ; U11.B2 21.75,19.58 C66.2 22.15,19.49 U11.C2 ; R21.1 v1(25.34,12.85) ; v1(28.74,11.98) 28.76,11.98 U14.B1 ; U6.B2 58.49,38.68 v1(58.67,38.86)
  TOP w0.254: C32.2 v1(35.56,14.57) ; C2.2 52.93,27.52 v2(53.42,27.52) 53.52,27.42 C7.2 ; J5.50 v1(35.6,40.22) ; U14.A2 30.22,12.44 v1(29.83,12.84) ; C84.2 v1(46.89,34.83) ; v1(27.08,0.89) 27.08,1.76 C28.2 ; C39.2 v1(48.61,18.61) ; v1(14.06,13.21) 14.06,13.19 14.55,12.69 P1.10 ; v1(29.16,43.04) 29.6,43.48 J5.79 ; C55.2 v1(53.23,33.29) ; C51.2 35.94,27.37 35.94,27.85 v2(36.09,28) ; v1(39.25,40.22) 38.8,39.77 J5.34 ; U10.4 21.96,27.7 v3(22.21,27.45) ; v1(48.16,12.57) 49.18,11.55 SW3.2 ; J5.9 43.6,42.84 v1(43.43,42.67) ; v2(40.16,26.78) 40.15,26.76 40.05,26.76 C52.2 ; U14.A1 29.21,12.44 v1(28.82,12.83) ; C8.2 v1(58.42,24.93) ; C54.1 v1(32.83,25.7) ; R58.2 v1(43.69,14.52) ; R58.2 v1(43.61,16.22) ; R58.2 v1(45.28,16.12) ; SW2.2 v1(53.4,17.65) ; v2(40.96,23.19) 40.91,23.19 40.66,22.94 40.66,22.16 C41.2 ; 56.48,37.68 v1(56.45,37.66) C23.2 ; C43.2 v1(32.61,18.61) ; U18.3 v1(47.02,30.73) ; J5.59 33.6,43.06 v1(33.46,42.92) ; v2(40.22,23.25) 40.14,23.25 39.63,23.75 C35.2 39.63,24.55 C34.2 38.74,24.56 C36.2 38.11,24.56 v2(37.87,24.32) ; v1(28.09,16.28) 28.65,15.72 U13.5 ; v1(24.36,15.24) 24.92,15.24 C68.2 ; J7.2 9.61,27.12 R47.2 11.33,25.4 v1(12.83,25.4) ; J5.44 v1(36.8,40.23) ; C49.2 v1(54.75,32.14) ; C3.2 52.1,23.8 v2(51.82,23.52) ; C13.2 15.08,9.52 v1(15.08,9.53) ; J5.19 41.61,43.82 v1(41.61,42.7) ; SW1.2 v1(58.56,29.98) ; v2(55.82,23.52) 55.94,23.64 C4.2 ; C81.2 36.22,34.96 v1(36.1,34.84) ; U17.3 v1(44.29,31.79) ; C46.2 v1(50.15,31.86) ; v1(21.88,12.67) 21.31,12.67 C20.2 ; J5.43 v1(36.8,42.95) ; C80.1 v1(33.36,10.56) ; 58.11,21.67 v1(58.63,22.2) ; C85.1 42.64,26.83 42.64,26.65 42.57,26.58 42.57,26.44 42.4,26.26 v2(41.64,26.26) ; v1(22.07,23.24) 22.45,23.24 C65.2 22.63,23.88 v1(22.07,23.88) ; P1.6 v1(3.43,10.29) ; v1(29.08,40.02) 29.35,40.02 29.44,39.92 29.44,39.91 29.6,39.75 J5.80 ; J5.10 v1(43.6,38.3) ; R51.1 v1(35.26,13.15) ; R8.1 v1(24.24,33.17) ; J5.20 v1(41.6,40.2) ; R48.1 27.39,29.16 v1(27.22,29.33) ; C33.2 41.09,24.16 v2(41.13,24.2) ; R9.1 v1(22.2,33.17) ; C5.2 55.3,27.24 v2(55.02,27.52) ; J5.69 v1(31.6,42.95) ; C1.2 v1(49.34,19.95) ; J5.49 v1(35.6,42.95) ; C82.2 v1(39.78,34.83) ; R49.1 v1(16.77,26.69) ; C26.2 v1(58.23,36) ; C48.2 v1(53.2,32.12) ; v1(44.84,42.84) 44.4,43.28 J5.5 ; C44.2 v1(34.32,18.61) ; C83.2 v1(43.34,34.83) ; C38.2 v1(46.96,18.61) ; U15.3 v1(37,31.79) ; C50.2 v1(40.28,17.65) ; C37.2 v1(45.31,18.61) ; v1(44.71,40.09) 44.4,39.78 J5.6 v1(44.4,38.28) ; C40.2 v1(50.26,18.61) ; J5.70 v1(31.6,40.11) ; v1(18.82,31.65) U3.4 ; v2(44.79,25.14) 44.61,24.96 C86.2 ; C45.2 v1(31.14,32.64) ; C77.1 v1(27.32,25.79) ; C72.1 v1(25.34,33.17) ; C12.2 v1(20.6,7.72) ; C47.2 v1(51.68,32.12) ; J5.60 v1(33.6,40.2) ; C6.2 v1(49.34,31.11) ; v2(36.65,22.26) 36.63,22.27 C42.2 ; R31.1 v1(47.29,25.6) ; J5.33 v1(38.8,42.95) ; v1(40.77,31.5) 40.16,31.5 39.91,31.75 U16.3
  TOP w0.381: C62.2 v1(27.57,25.13)
  LY2-GND w0.254: U4.17 7.27,17.32 ; U4.17 6.82,16.87 ; U4.17 7.27,16.41 ; U4.17 7.73,16.87 ; 52.09,34.67 U9.15 ; U9.15 52.54,35.13 ; U9.15 51.63,35.13 ; U9.15 52.09,35.59 ; 22.64,28.34 U10.25 ; U10.25 23.56,28.34 ; U10.25 23.1,28.8 ; U10.25 23.1,27.88
  LY7-SIG w0.381: v1(18.67,35.43) v1(19.29,34.81)
  LY9-GND w0.254: U9.15 52.54,35.13 ; U9.15 51.63,35.13 ; U9.15 52.09,35.59 ; U9.15 52.09,34.67 ; 6.82,16.87 U4.17 ; U4.17 7.27,17.32 ; U4.17 7.73,16.87 ; U4.17 7.27,16.41 ; 23.1,27.88 U10.25 ; U10.25 23.1,28.8 ; U10.25 22.64,28.34 ; U10.25 23.56,28.34
  BOTTOM w0.203: U1.R18 U1.R17 36.59,22.27 36.6,22.26 v2(36.65,22.26) 36.64,22.27 U1.P16 ; U1.M8 40.64,23.38 40.75,23.26 40.84,23.26 40.91,23.19 v2(40.96,23.19) ; U1.M8 40.92,23.77 41.13,23.97 v2(41.13,24.2) 41.04,24.2 40.97,24.27 U1.L8 U1.L9 ; U1.M8 U1.M9 ; U1.L9 U1.K9 U1.K10 ; U1.L9 U1.M9 ; U1.J11 U1.H11 ; U1.H11 U1.H12 38.35,26.06 v2(38.13,26.06) 38.25,25.93 38.25,25.69 38.64,25.3 U1.J12 ; U1.H11 39.14,26.1 38.89,26.35 v2(38.83,26.35) ; U1.H11 U1.H10 ; v2(41.68,25.21) 41.68,24.81 U1.K6 ; v2(41.64,26.26) U1.G5 U1.G4 ; v2(40.16,26.78) 40.15,26.76 U1.F10 ; U1.A2 43.64,29.58 v2(43.97,29.91) ; U12.C3 v1(32.89,6.73) ; U12.C2 34.29,6.94 v1(34.29,6.86) ; v2(40.22,23.25) 40.2,23.27 ; 40.2,23.27 40.14,23.33 U1.M9 ; 40.2,23.27 U1.N10 ; U1.B19 34.97,28.76 34.95,28.79 34.86,28.79 v2(34.62,29.03) ; C15.2 v1(10.58,19.19) ; U1.W2 43.64,20.26 v2(44.15,19.75) 44.15,20.25 U1.W1 ; U1.K14 37.64,24.55 v2(37.87,24.32) 38.14,24.59 U1.K13 ; U1.D18 35.85,27.76 v2(36.09,28) ; U1.B1 44.57,29.2 v2(44.57,29.63) 44.5,29.63 U1.A1 ; C19.2 v1(5.09,19.19) ; U1.M9 U1.M10 ; U1.V1 44.22,20.77 v2(44.98,20) ; U1.A19 35.13,29.28 v2(35.13,29.78) 35.64,29.27 U1.A18 ; U12.B1 v1(35.58,8.14) ; U12.C1 v1(35.33,6.91) ; U19.1 v1(16.58,23.55)
  BOTTOM w0.254: v1(17.63,9.89) 16.88,9.89 U5.29 ; v1(13.04,22.8) 12.7,23.14 C71.1 ; v1(17.63,10.78) 16.87,10.78 U5.29 ; U5.29 15.99,10.78 v1(15.22,10.78) 15.22,11.56 U5.26 14.48,11.59 14.48,10.93 v1(14.33,10.78) ; J3.9 v1(37.24,6.92) ; v1(18.54,2.41) 18.54,1.84 C18.1 ; v1(44.84,42.84) 44.84,42.05 C57.2 ; v1(18.54,3.68) 18.54,4.31 C17.1 ; J4.5 v1(25.68,0.99) ; U5.17 v1(15.08,9.53) ; C60.2 44.97,40.35 v1(44.71,40.09) ; v1(18.65,10.78) 18.65,11.33 U5.28 ; U5.32 19.68,8.68 v1(19.68,7.75) ; J3.2 43.16,10.96 v1(42.32,11.81) 41.73,12.4 C25.2 ; v1(36.8,40.23) 36.95,40.08 J2.12 ; R55.2 18.16,24.52 v1(18.16,24.78) ; v1(27.08,0.89) 27.08,2.67 J4.3 ; U5.5 v1(17.78,16.23) ; U5.31 v1(19.69,16.25) ; U5.15 16.89,8.67 v1(16.89,7.75) ; C87.1 32.94,28.35 v1(33.01,28.35) ; C21.2 v1(25.01,37.34) ; J3.11 v1(38.37,2.54) ; v1(36.6,9.27) 36.22,9.65 C75.1 ; J2.7 v1(31.95,37.39) ; v1(18.82,31.65) 18.65,31.65 C14.2 ; U2.D7 v2(53.42,27.52) ; v1(20.83,8.38) 21.73,8.38 C11.2 ; J6.2 11.96,24.75 v1(13.25,24.75) ; U2.C3 v2(54.22,23.52) ; U2.J1 v2(48.62,21.92) ; R13.2 v1(10.58,12.9) ; U2.B7 v2(55.02,27.52) ; v1(53.98,37.34) 53.47,36.83 U9.9 ; U5.9 19.52,12.57 19.18,12.57 v1(18.67,13.08) ; C30.1 v1(32.66,20.73) ; U5.13 18.67,8.66 v1(18.67,7.62) ; U2.E3 v2(51.82,23.52) ; C58.2 v1(46.88,40.07) ; v1(50.16,38.35) 50.64,37.88 U9.7 ; R60.2 21.98,33.17 v1(22.2,33.17) ; R12.2 v1(3.31,14.89) ; C56.2 41.61,42.32 v1(41.61,42.7) 41.55,42.64 J2.15 ; C29.1 v1(32.66,23.2) ; U5.33 12.75,8.69 v1(12.32,8.26) ; U5.30 v1(12.26,15.2) ; C22.2 v1(26.91,37.34) ; C73.2 v1(31.73,6.94) ; U9.12 v1(54.21,35.33) ; U4.9 7.02,14.52 v1(6.48,13.97) ; v1(17.63,13.2) 16.78,13.2 U5.25 16.98,14.09 v1(17.63,14.09) ; J3.12 v1(48.29,10.54) ; C59.2 v1(46.88,42.65) ; U2.A1 v2(55.82,21.92) ; C53.2 v1(40.69,32.18) ; v1(29.61,7.36) C74.2 v1(30.46,6.39) ; U9.13 53.44,34.83 v1(53.98,34.29) ; C61.2 41.6,40.47 v1(41.6,40.2) ; R46.1 v1(38.37,11.93) ; J2.1 v1(25.95,40.09) ; J2.16 v1(24.65,41.03) ; R54.1 v1(17.78,20.45) ; C88.1 32.96,29.83 v1(33.16,29.63) ; U2.A3 v2(55.82,23.52) ; U5.7 v1(18.57,14.19) ; J4.9 v1(22.12,2.79) ; U9.10 v1(54.23,36.33) ; C10.2 v1(1.64,24.73)
  BOTTOM w0.381: J1.5 v1(18.67,35.43)
  BOTTOM w0.508: U5.27 U5.29 ; U5.27 U5.28 ; U5.27 U5.26 ; U5.27 U5.25 ; F1.2 v1(11.62,30.35) ; F1.2 v1(13.71,30.23) ; F1.2 v1(13.53,32.26)
  vias: v1(1.65,12.68) v1(1.65,8.26) v1(2.42,13.57) v1(2.67,11.66) v1(2.67,8.26) v1(3.18,14.2) v1(3.43,12.42) v1(3.68,8.26) v1(4.07,13.19) v1(4.96,14.07) v1(5.72,10.65) v1(6.48,19.54) v1(6.73,9.27) v1(6.73,8.26) v1(6.99,10.65) v1(7.88,18.9) v1(8.26,10.65) v1(8.26,9.27) v1(8.64,8.36) v1(9.27,9.27) v1(9.53,19.28) v1(9.53,10.65) v1(10.29,8.26) v1(10.42,15.09) v1(11.31,15.09) v1(11.3,8.26) v1(11.81,14.2) v1(11.81,13.31) v1(11.81,12.42) v1(12.32,18.9) v1(12.32,17.5) v1(12.96,19.66) v1(12.96,18.14) v1(13.47,17.5) v1(13.85,18.77) v1(14.86,18.39) v1(15.62,6.6) v1(15.62,5.59) v1(15.62,4.57) v1(15.62,3.56) v1(15.62,2.54) v1(15.62,1.02) v1(15.88,17.25) v1(16.01,18.39) v1(16.64,6.6) v1(16.64,5.59) v1(16.64,4.57) v1(16.64,3.56) v1(16.64,2.54) v1(16.64,1.02) v1(16.89,16.87) v1(17.15,18.39) v1(18.16,1.02) v1(18.42,17.88) v1(18.54,22.48) v1(18.65,9.89) v1(18.67,6.6) v1(18.67,5.59) v1(19.18,22.48) v1(19.18,4.57) v1(19.18,3.05) v1(19.18,1.02) v1(19.43,17.25) v1(19.68,6.6) v1(19.68,5.59) v1(19.68,3.56) v1(19.68,2.03) v1(20.7,10.65) v1(20.7,6.6) v1(20.7,5.59) v1(20.7,4.57) v1(20.7,3.56) v1(20.7,2.54) v1(20.7,1.52) v1(22.63,19.68) v1(25.69,10.17) v1(26.33,10.17) v1(27.3,20.95) v1(27.3,20.19) v1(28.07,20.95) v1(28.07,20.19) v3(7.27,17.87) v3(7.27,15.87) v3(8.27,17.87) v3(8.27,16.87) v3(8.27,15.87) v3(21.32,28.34) v3(21.32,26.56) v3(23.1,26.56) v3(50.69,36.53) v3(50.69,35.13) v3(51.39,35.83) v3(52.09,36.53)
GND_EARTH: length 156.2
  TOP w0.381: P1.12 15.39,17.81 14.73,17.14 14.1,17.14 13.6,16.65 13.6,15.68 P1.11 17.34,11.94 18.67,11.94 20.19,10.41 20.2,10.41 20.49,10.12 20.92,10.12 21.08,10.29 22.61,10.29 23.75,9.14 23.75,7.24
  TOP w0.508: 11.96,23.72 11.25,24.43 9.07,24.43 7.72,25.78 7.72,28 20.89,41.18 MH1.1 ; 11.96,23.72 P1.14 13.11,23.72 13.72,23.11 13.72,21.46 14.22,20.95 14.33,20.95 P1.12 ; 11.96,23.72 11.83,23.72 11.02,22.9 7.02,22.9 5.98,21.87 2.84,21.87 ; 3.95,14.11 1.46,11.63 P1.16 ; 3.95,14.11 4.29,13.77 4.31,13.77 4.65,13.43 4.65,13.4 6.37,11.68 9.91,11.68 11.16,10.43 P1.9 ; 3.95,14.11 3.95,15.72 2.84,16.83 2.84,21.87 ; 2.84,21.87 1.95,22.76 1.95,23.17 P1.15 ; 23.75,7.24 23.75,5.97 26.72,3 MH3.1 34.79,3 45.5,13.71 R58.1 47.8,13.71 48.01,13.92 SW3.3 49.24,15.17 53.18,19.11 54.35,19.11 SW2.3 56.4,20.85 56.4,21.79 59.41,24.81 59.41,27.47 57.58,29.3 57.58,30.88 SW1.3 58.38,33.26 54.81,36.84 MH2.1
BAT_V_SW: length 36.1
  LY8-SIG w0.102: v2(42.7,29.78) 42.32,30.16 41.17,30.16 40.2,31.13 37.97,31.13 37.52,30.68 37.52,30.02 36.85,29.35 36.11,29.35 35.3,30.16 32.56,30.16 31.52,29.12 31.52,28.35 31.52,28.35 31.52,28.04 31.77,27.78 31.77,25.98 29.55,23.76 24.14,23.76 23.11,22.73 21.84,22.73 20.82,23.76 18.58,23.76 v1(17.06,22.24)
  BOTTOM w0.099: R54.2 v1(17.06,22.24) 16.78,21.96 R57.1 ; v2(42.7,29.78) 42.7,29.32 U1.A4
BAT_VSENSE_EN: length 36.8
  LY8-SIG w0.102: v1(16.97,23.03) 16.98,23.03 18.34,24.38 22.86,24.38 23.07,24.17 29.19,24.17 31.43,26.41 31.43,27.58 31.21,27.79 31.21,29.77 31.91,30.47 35.28,30.47 35.55,30.19 36.53,30.19 36.73,30.4 36.73,30.69 36.73,30.69 36.73,30.77 37.37,31.4 40.32,31.4 40.75,30.97 42.78,30.97 v2(43.2,30.54)
  BOTTOM w0.099: U19.2 16.7,22.75 16.97,23.01 v1(16.97,23.03) 16.98,23.03 17.05,23.1 R55.1 ; U1.B4 42.92,29.04 42.92,29.5 43.2,29.78 v2(43.2,30.54)
BATTERY_THERMISTOR: length 11.4
  TOP w0.254: U10.9 20.21,27.71 R44.2 18.13,27.18 15.37,27.18 14.22,26.04 12.16,26.04 R47.1 10.31,27.88 J7.1
BC_CSZ: length 29.1
  TOP w0.099: R8.2 v1(24.24,30.53) 23.46,29.75 U10.1
  LY7-SIG w0.102: v2(41.49,25.72) 41.68,25.91 41.8,25.91 41.99,26.11 41.99,26.12 42,26.12 42,26.41 41.99,26.41 41.99,26.43 41.8,26.63 41.8,27.03 42.01,27.24 42.29,27.24 42.53,27.49 42.53,27.75 41.64,28.65 40.66,28.65 40.47,28.84 38.2,28.84 37.98,28.62 37.97,28.62 37.76,28.41 37.76,28.4 37.68,28.31 37.68,27.8 37.36,27.48 37.29,27.48 37.29,27.48 36.99,27.48 36.99,27.48 36.91,27.48 36.67,27.24 35.65,27.24 35.26,26.86 34.36,26.86 34.08,27.13 33.68,27.13 33.23,26.68 33.23,26.58 33,26.36 32.48,26.36 31.25,27.58 29.62,27.58 28.88,26.84 28.28,26.84 26.87,28.24 26.52,28.24 v1(24.24,30.53)
  BOTTOM w0.099: v2(41.49,25.72) 41.68,25.91 41.79,25.91 41.87,25.99 42.42,25.99 U1.H4
BC_EN1: length 49.7
  TOP w0.099: U10.2 22.96,30.27 v1(23.22,30.53) R1.1
  LY8-SIG w0.102: v2(45.49,28.64) 45.49,33.04 44.35,34.18 44.35,34.94 43.21,36.08 43.21,37.53 42.21,38.54 42.21,43 41.62,43.58 28.17,43.58 23.71,39.12 23.71,32.47 23.22,31.98 v1(23.22,30.53)
  BOTTOM w0.099: U1.E2 43.74,27.37 44.47,27.37 44.91,27.81 44.91,27.99 45.12,28.2 45.3,28.2 45.49,28.39 v2(45.49,28.64)
BC_EN2: length 27.5
  TOP w0.099: U10.3 22.46,30.27 v1(22.2,30.53) R9.2
  LY7-SIG w0.102: v1(22.2,30.53) 25.41,27.32 27.27,27.32 28.21,26.38 31.94,26.38 32.18,26.14 33.3,26.14 33.54,26.38 33.98,26.38 34.09,26.49 35.64,26.49 35.86,26.71 36.4,26.71 36.77,26.35 37.91,26.35 38.04,26.48 38.26,26.48 38.47,26.69 38.47,26.98 38.47,26.98 38.47,27.23 38.48,27.24 38.48,28.05 39.05,28.62 40.31,28.62 40.52,28.41 40.52,28.23 40.94,27.8 41.98,27.8 v2(42.15,27.63)
  BOTTOM w0.099: v2(42.15,27.63) 42.15,27.62 42.15,27.51 42.39,27.26 U1.E3
BC_INT: length 30.4
  TOP w0.099: U10.8 19.18,28.2 R4.1 18.66,29.22 v1(18.16,29.72)
  LY4-SIG w0.102: v1(18.16,29.72) 18.16,25.53 22.23,21.46 28.42,21.46 28.7,21.18 33.04,21.18 34.06,20.16 36.56,20.16 36.97,19.75 v2(38.38,19.75)
  BOTTOM w0.099: v2(38.38,19.75) 38.64,20.01 U1.W12
BC_SCL: length 35.4
  TOP w0.099: R2.1 v1(20.17,30.53) 20.96,29.74 U10.6
  LY4-SIG w0.102: v1(20.17,30.53) 20.17,25.74 21.27,24.64 22.1,24.64 24.89,21.84 26.92,21.84 v1(27.43,22.35)
  LY7-SIG w0.102: v1(27.43,22.35) 29.15,24.07 31.54,24.07 32.02,23.58 32.82,23.58 33.05,23.36 33.05,23.3 33.15,23.2 33.99,23.2 34.22,23.42 34.78,23.42 35.12,23.09 35.12,21.23 35.44,20.91 41.9,20.91 41.96,20.85 42.62,20.85 v2(42.89,21.12)
  BOTTOM w0.099: U1.V3 43.14,20.87 v2(42.89,21.12)
BC_SDA: length 39.2
  TOP w0.099: U10.5 21.46,30.25 v1(21.19,30.53) R3.1
  LY4-SIG w0.102: v1(26.67,22.35) 25.65,22.35 22.61,25.4 21.28,25.4 20.65,26.02 20.65,29.99 v1(21.19,30.53)
  LY7-SIG w0.102: v1(26.67,22.35) 27.11,21.91 28.13,21.91 29.66,23.44 31.67,23.44 32.29,22.81 33.01,22.81 33.15,22.95 33.96,22.95 34.62,22.29 34.62,19.84 35.24,19.22 37.82,19.22 37.98,19.38 40.85,19.38 41.02,19.2 41.02,18.28 41.6,17.7 43.3,17.7 43.71,18.11 v2(43.71,18.99)
  BOTTOM w0.099: U1.W3 43.46,19.95 43.46,19.24 v2(43.71,18.99)
BT1P8_CTS: length 8.9
  LY3-SIG w0.102: v1(16.88,16.04) 16.05,15.2 13.73,15.2 13.09,15.84 v1(10.44,15.84)
  BOTTOM w0.099: v1(10.44,15.84) 10.16,16.12 U4.6 ; U5.4 v1(16.88,16.04)
BT1P8_NSHUTD: length 14.1
  TOP w0.099: v1(9.53,12.83) 10.03,12.32 11.05,12.32 11.68,11.68 15.11,11.68 16,10.79 v1(16,7.75)
  BOTTOM w0.099: U4.7 9.54,13.59 R13.1 9.53,13.58 v1(9.53,12.83) ; v1(16,7.75) 16,8.65 U5.16
BT1P8_RTS: length 6.4
  LY3-SIG w0.102: v1(10.39,17.62) 10.39,17.16 10.94,16.62 13.64,16.62 v1(14.18,16.07)
  BOTTOM w0.099: U4.3 v1(10.39,17.62) ; v1(14.18,16.07) U5.1
BT1P8_RX: length 7
  LY3-SIG w0.102: v1(10.39,16.62) 10.78,16.23 13.16,16.23 13.83,15.55 14.6,15.55 v1(15.08,16.04)
  BOTTOM w0.099: U4.5 v1(10.39,16.62) ; v1(15.08,16.04) U5.2
BT1P8_SLOW_CK: length 17.6
  LY7-SIG w0.102: v1(20.68,13.29) 19.55,14.42 19.55,15.87 19.53,15.87 17.63,17.77 14.14,17.77 12.07,19.83 v1(8.52,19.83)
  BOTTOM w0.099: U4.1 v1(8.52,19.83) ; U5.8 v1(20.68,13.29)
BT1P8_TX: length 7.7
  LY3-SIG w0.102: v1(10.99,17.12) 14.9,17.12 v1(15.98,16.04)
  BOTTOM w0.099: U5.3 v1(15.98,16.04) ; U4.4 v1(10.99,17.12)
BT_ANT: length 7.9
  BOTTOM w0.381: L3.2 17.73,2.55 C18.2 17.73,1.71 E1.1
BT_ANTENNA: length 5.1
  BOTTOM w0.381: L3.1 17.75,4.42 C17.2 17.73,8.62 U5.14
BT_CTS: length 50.4
  LY7-SIG w0.102: v1(5.03,16.12) 4.04,16.12 3.58,16.57 3.58,18.84 15.25,30.5 19.43,30.5 20.06,31.14 25.56,31.14 26.55,30.15 27.34,30.15 27.67,29.81 28.34,29.81 28.55,29.6 28.55,28.93 28.8,28.68 30.85,28.68 31.52,28.02 31.52,27.76 32.12,27.15 33.33,27.15 33.61,27.43 34.3,27.43 34.39,27.34 34.86,27.34 37.67,30.14 38.92,30.14 v2(39.01,30.06)
  BOTTOM w0.099: U1.B12 38.86,28.99 38.86,29.15 38.86,29.15 38.86,29.38 39.01,29.53 v2(39.01,30.06) ; U4.11 v1(5.03,16.12)
BT_NSHUTD: length 74.1
  LY4-SIG w0.102: v1(4.92,15.08) 2.04,12.19 2.04,10.03 2.8,9.27 4.7,9.27 5.59,10.16 10.4,10.16 11.28,9.27 13.08,9.27 13.72,8.64 18.29,8.64 19.3,9.65 19.3,10.29 21.08,12.06 27.56,12.06 28.45,11.18 29.59,11.18 30.73,12.32 34.92,12.32 37.08,10.16 37.08,7.75 37.72,7.11 40.51,7.11 45.72,12.32 45.72,20.74 v2(46.25,21.27)
  BOTTOM w0.099: U4.10 5.46,15.62 v1(4.92,15.08) 4.38,15.62 R12.1 ; U1.T2 43.95,21.45 44.42,21.45 44.42,21.44 44.62,21.44 45.3,20.77 45.74,20.77 v2(46.25,21.27)
BT_RTS: length 47.7
  LY7-SIG w0.102: v2(40.71,27.26) 40.54,27.1 40.54,25.88 39.02,24.36 38.65,24.36 38.25,23.97 37.72,23.97 37.06,24.63 37.06,24.76 36.78,25.04 36.49,25.04 36.42,24.96 34.41,24.96 34.22,24.77 34.22,24.36 34.01,24.15 32.65,24.15 31.5,25.3 28.72,25.3 28.18,24.75 26.53,24.75 24.51,22.73 21.84,22.73 20.92,23.65 18.14,23.65 17.14,22.65 16.82,22.65 16.1,22.65 15.07,23.68 10.92,23.68 7.76,20.51 7.76,19.72 5.64,17.6 4.56,17.6 v1(4.35,17.39)
  BOTTOM w0.099: U1.D8 40.64,27.36 40.71,27.29 v2(40.71,27.26) ; U4.14 4.57,17.62 v1(4.35,17.39)
BT_RX: length 49
  LY7-SIG w0.102: v1(4.43,16.62) 4.12,16.62 3.87,16.87 3.87,18.08 4.42,18.64 6.2,18.64 7.48,19.92 7.48,20.84 10.79,24.15 15.22,24.15 15.43,23.94 18,23.94 18.32,24.26 22.63,24.26 24.92,26.54 27.13,26.54 27.88,25.79 31.66,25.79 32.55,24.91 34.01,24.91 34.33,25.23 35.37,25.23 35.83,25.69 36.48,25.69 37.49,24.68 38.82,24.68 39.8,25.66 39.8,26.97 40.17,27.33 40.25,27.33 40.3,27.38 40.31,27.38 40.52,27.59 40.52,27.88 40.51,27.88 40.51,27.91 v2(40.16,28.26)
  BOTTOM w0.099: U1.C8 v2(40.16,28.26) ; U4.12 v1(4.43,16.62)
BT_SLOW_CK: length 41.2
  LY7-SIG w0.102: v1(7.02,20.05) 7.02,21.02 12.29,26.29 14.1,26.29 14.45,25.94 18.08,25.94 18.47,25.55 22.96,25.55 24.34,26.93 27.15,26.93 27.95,26.13 31.77,26.13 32.64,25.25 33.25,25.25 33.67,25.67 35.49,25.67 35.72,25.9 36.61,25.9 36.91,25.61 37.76,25.61 37.86,25.7 38.27,25.7 38.31,25.74 38.71,25.74 38.96,25.99 38.98,25.99 39.19,26.2 39.19,27.49 39.11,27.57 v2(39.11,28.13)
  BOTTOM w0.099: U1.C12 39.01,28.26 39.11,28.16 v2(39.11,28.13) ; U4.16 v1(7.02,20.05)
BT_TX: length 46.9
  LY7-SIG w0.102: v1(5.11,17.12) 5.55,17.12 8.13,19.69 8.13,20.17 11.27,23.31 14.82,23.31 16.33,21.81 17.49,21.81 17.91,22.23 17.91,22.61 18.49,23.18 20.76,23.18 21.72,22.23 25.27,22.23 27.3,24.26 28.57,24.26 29.15,24.83 31.45,24.83 32.34,23.94 34.09,23.94 34.36,24.21 35.22,24.21 35.71,23.72 36.38,23.72 37.53,22.57 37.88,22.57 38.4,23.1 38.4,23.58 38.79,23.97 39.25,23.97 40.76,25.47 40.76,26.56 v2(41.03,26.83)
  BOTTOM w0.099: v2(41.03,26.83) 41.03,26.87 41.14,26.98 U1.E7 ; U4.13 v1(5.11,17.12)
CSZ: length 2.2
  BOTTOM w0.099: R14.1 29.95,36.65 J2.5
CSZP: length 20.7
  LY8-SIG w0.102: v1(29.91,34.8) 30.82,33.9 37.33,33.9 38.81,32.42 40.15,32.42 40.3,32.57 41.11,32.57 42,31.68 42.64,31.68 43.6,30.72 43.6,29.82 42.72,28.94 41.86,28.94 v2(41.18,28.26)
  BOTTOM w0.099: U1.C6 v2(41.18,28.26) ; R14.2 v1(29.91,34.8)
DATAEN_CMD: length 15
  TOP w0.099: v1(50.12,33.42) 50.16,33.38 50.16,33.03 R38.1
  LY4-SIG w0.102: v1(50.12,33.42) 50.12,32.64 48.77,31.28 48.77,29.87 46.88,27.98 46.88,24.91 45.92,23.95 45.24,23.95 44.82,23.53 v2(44.66,23.53)
  BOTTOM w0.099: U1.N1 44.39,23.27 v2(44.66,23.53) ; U9.1 50.64,33.75 50.32,33.42 v1(50.12,33.42)
DATAEN_CMD_B: length 23.8
  TOP w0.099: R34.2 49.4,33.43 v1(49.4,33.43) 49.39,33.42 R38.2 ; v1(35.88,42.33) 36,42.45 J5.47
  LY3-SIG w0.102: v1(49.4,33.43) 49.4,33.43 49.4,37.85 48.9,38.35 46.97,38.35 45.09,40.24 45.09,40.38 43.21,42.26 40.33,42.26 39.15,43.43 37.85,43.43 36.96,42.55 36.1,42.55 v1(35.88,42.33)
DIN: length 2.2
  BOTTOM w0.099: J2.8 32.95,36.62 R16.1
DINP: length 14
  LY7-SIG w0.102: v2(42.44,30.54) 42.44,31.56 41.37,32.63 40.37,32.63 38.94,34.07 33.66,34.07 v1(32.96,34.76)
  BOTTOM w0.099: R16.2 v1(32.96,34.76) ; U1.A5 42.16,29.29 42.16,30.26 v2(42.44,30.54)
DLPC_HOST_IRQ: length 32.2
  TOP w0.099: v2(42.99,24.23) 44.11,23.11 45.27,23.11 45.27,23.12 45.57,23.12 45.57,23.11 46.48,23.11 47.7,24.33 47.7,34.62 47.59,34.73 47.59,35.04 47.62,35.08 47.62,35.94 47.24,36.32 47.24,36.83 46.61,37.47 42.93,37.47 42.29,38.1 v1(41.66,38.1) ; v1(41.34,41.44) 41.34,41.95 40.8,42.49 J5.23
  LY4-SIG w0.102: v1(41.66,38.1) 41.66,39.12 41.15,39.62 41.15,40.45 41.34,40.64 v1(41.34,41.44)
  BOTTOM w0.099: U1.M3 43.14,24.13 43.04,24.23 v2(42.99,24.23) ; v1(41.66,38.1) 41.4,37.85 R37.1
DLPC_XLAT0_TIVA: length 20
  TOP w0.099: J5.39 v1(37.6,42.54)
  LY4-SIG w0.102: v1(37.6,42.54) 38.26,41.88 38.26,41.19 38.66,40.79 39.25,40.79 41.02,39.02 41.02,35.39 42.44,33.98 42.44,32.31 43.58,31.16 43.58,30.18 43.5,30.09 43.5,29.25 v2(42.57,28.32)
  BOTTOM w0.099: v2(42.57,28.32) 42.57,28.12 42.44,27.99 41.89,27.99 41.82,27.91 41.79,27.91 U1.D6
DLPC_XLAT1_TIVA: length 20
  TOP w0.099: J5.41 37.2,41.47 v1(37,41.26)
  LY4-SIG w0.102: v2(41.57,27.34) 41.57,27.7 41.82,27.95 41.82,29.16 42.23,29.57 42.23,30.18 42.01,30.39 42.01,31.27 41.93,31.34 41.93,33.48 41.93,33.73 40.99,34.68 40.97,34.68 40.83,34.82 40.44,34.82 39.1,36.16 39.1,38.82 37.89,40.03 37.89,40.6 37.22,41.26 v1(37,41.26)
  BOTTOM w0.099: U1.D7 v2(41.57,27.34)
DOUT_S: length 20.9
  LY7-SIG w0.102: v2(41.81,29.78) 41.26,30.33 40.89,30.33 38.8,32.42 32.74,32.42 30.45,34.71 30.45,35.37 31.24,36.16 32.62,36.16 v1(33.95,37.49)
  BOTTOM w0.099: U1.B5 41.81,29.1 v2(41.81,29.78) ; J2.9 v1(33.95,37.49)
DRDYZ: length 12
  BOTTOM w0.099: J2.10 34.95,36.05 35.68,35.33 35.68,34.05 38.92,30.81 38.92,30.52 38.48,30.08 38.48,29.11 U1.B13
EN: length 72.6
  TOP w0.099: v1(44.2,36.57) R53.2 44.98,36.52 R52.1 ; U14.B2 30.73,11.88 v1(30.73,12.95)
  TOP w0.203: v1(20.85,19.05) 21.03,19.05 U11.A2
  LY3-SIG w0.102: v1(30.73,12.95) 30.73,13.1 30.15,13.68 27.48,13.68 24.61,16.55 23.35,16.55 v1(20.85,19.05)
  LY8-SIG w0.102: v1(44.2,36.57) 46.61,36.57 48.77,34.42 52.83,34.42 53.72,33.53 55.06,33.53 56.41,32.18 56.41,21.91 55.1,20.6 53.34,20.6 52.92,20.18 52.92,18.59 50.29,15.96 47.85,15.96 47.3,15.41 42.46,15.41 41.43,16.45 35.63,16.45 34.55,15.38 32.52,15.38 31.11,13.97 31.11,13.17 30.89,12.95 v1(30.73,12.95)
FLASH_DI_TIVA: length 41.6
  TOP w0.099: J5.25 40.4,41.99 40.84,41.55 v1(40.84,40.68) ; v2(36.14,24.26) 35.15,24.26 35.08,24.19 34.25,24.19 34.11,24.05 30.94,24.05 29.99,25 29.99,26.14 29.82,26.31 29.82,27.25 28.96,28.11 v1(28.13,28.11)
  LY8-SIG w0.102: v1(28.13,28.11) 27.5,28.74 27.12,28.74 26.53,29.33 26.53,30.31 27.02,30.79 27.02,33.49 29.75,36.22 36.72,36.22 37.32,36.82 37.32,38.62 38.2,39.5 38.2,41.37 38.57,41.74 40.55,41.74 40.84,41.46 v1(40.84,40.68)
  BOTTOM w0.099: U1.K17 v2(36.14,24.26)
HSYNC_CS: length 38.5
  TOP w0.099: v1(35.91,40.83) 36,40.74 J5.48
  LY3-SIG w0.102: v2(45.42,23.53) 45.21,23.53 44.78,23.95 44.07,23.95 44.07,23.95 44.02,23.95 43.85,24.12 43.85,24.68 44.05,24.88 44.05,28.42 43.18,29.28 43.18,29.84 42.81,30.21 42.81,31.99 41.87,32.93 41.87,34.58 41.48,34.97 40.94,34.97 40.7,34.73 40.7,34.29 39.84,33.42 39.6,33.42 39.47,33.55 39.47,33.83 40.24,34.6 40.24,35.36 39.91,35.69 39.57,35.69 39.23,35.35 39.23,34.47 38.94,34.18 38.74,34.18 38.23,34.69 38.23,35.11 39.67,36.54 39.67,36.83 39.56,36.94 39.31,36.94 38.97,36.6 38.06,36.6 37.7,36.24 36.47,36.24 36.14,36.58 36.14,37.07 36.53,37.47 36.53,37.73 37.33,38.53 37.33,39.08 36.41,40.01 36.41,40.72 36.3,40.83 v1(35.91,40.83)
  BOTTOM w0.099: v2(45.42,23.53) 44.88,22.99 44.26,22.99 44.26,22.99 44.03,22.99 44.03,22.99 43.92,22.99 U1.N2
